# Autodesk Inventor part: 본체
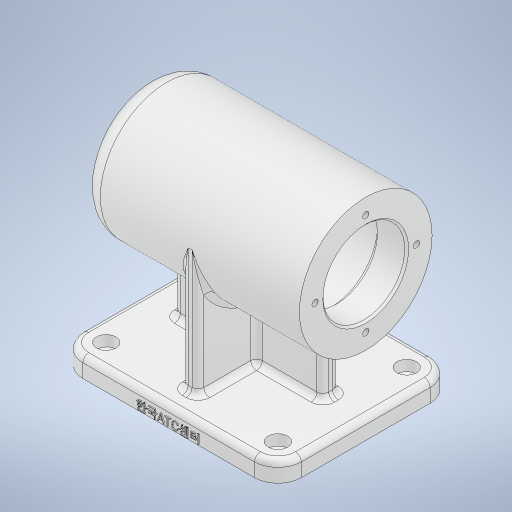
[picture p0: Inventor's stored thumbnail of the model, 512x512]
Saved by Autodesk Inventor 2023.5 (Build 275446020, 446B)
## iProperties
Created: 2026-08
Part Number: 본체
Material: 알루미늄 6061
Document SubType Name: Modeling
Designer: 1강의실14
Density: 2.7 g/cm^3
Appearance: 알루미늄 - 평지
Mass: 1025.89 g
Surface Area: 757.812 cm^2
Volume: 379.96 cm^3
Author: 1강의실14
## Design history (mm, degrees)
sketch "스케치1"
  geometry: L1 (56, 45)-(-56, 45); L2 (-56, 45)-(-56, -45); L3 (-56, -45)-(56, -45); L4 (56, -45)-(56, 45); L5 (56, 45)-(-56, -45); L6 (-56, 45)-(56, -45); 1 further point
  constraints: 12 end point, 2 midpoint, 2 parallel, 1 horizontal, 1 perpendicular
  dimensions: "d0" = 112 distance of L3.end L2.end; "d1" = 90 distance of L1.end L2.end
extrude "돌출1" new body sketch "스케치1" distance "d2" = 10; taper "d3" = 0 deg
sketch "스케치2"
  geometry: L1 (0, 0)-(0, 74); L2 (0, 74)-(44.651, 74); L3 (56, 0)-(-56, 0) reference; L4 (-46, 108)-(56, 108); L5 (56, 108)-(56, 96); L6 (55, 95)-(41, 95); L7 (41, 95)-(41, 95); L8 (38, 98)-(-10, 98); L9 (-13, 95)-(-13, 95); L10 (-13, 95)-(-24.4, 95); L11 (-25, 94.4)-(-25, 91.5); L12 (-25, 91.5)-(-43, 91.5); L13 (-43, 91.5)-(-43, 90); L14 (-43, 90)-(-46.4, 90); L15 (-50, 74)-(-56, 74); L16 (-56, 74)-(-56, 98); L17 (-47, 89.4)-(-47, 84.5); L18 (-47, 84.5)-(-47, 84.5); L19 (-50, 81.5)-(-50, 74); L20 (55, 95)-(56, 96); A1 r 0.6 centre (-46.4, 89.4) between (-46.4, 90) and (-47, 89.4); A2 r 0.6 centre (-24.4, 94.4) between (-24.4, 95) and (-25, 94.4); A3 r 10 centre (-46, 98) between (-46, 108) and (-56, 98); A4 r 3 centre (-10, 95) between (-10, 98) and (-13, 95); A5 r 3 centre (38, 95) between (41, 95) and (38, 98); A6 r 3 centre (-47, 81.5) between (-47, 84.5) and (-50, 81.5); 12 further points
  constraints: 38 end point, 16 point on line, 14 perpendicular, 12 point on circle, 12 tangent, 6 centre point, 2 collinear, 2 midpoint, 2 vertical, 1 equal radius, 1 horizontal
  dimensions: "d4" = 74 distance between parallel lines of L2 L3; "d5" = 112 distance of point (-56, 108) L4.end; "d6" = 54 distance of point (41, 98) point (-13, 98); "d7" = 15 distance of point (56, 95) L6.end; "d8" = 18 distance of L11.end L12.end; "d9" = 103 horizontal distance of point (56, 95) point (-47, 90); "d10" = 42 diameter of point (48, 95) L2; "d11" = 68 diameter of L4 L2; "d12" = 48 diameter of L8 L2; "d17" = 81 horizontal distance of L4.end point (-25, 95); "d18" = 3 distance of L17.end point (-50, 84.5); "d19" = 21 diameter of L18 L2; "d20" = 32 diameter of L14 L2; "d21" = 35 diameter of L12 L2; "d22" = 0.6 radius of A1; "d23" = 0.6 radius of A2 (derived); "d24" = 10 radius of A3 (derived); "d25" = 3 radius of A4; "d26" = 1 distance of L6.start point (56, 95); "d27" = 1 distance of L5.end point (56, 95) (= d26); "d28" = 3 radius of A6 (derived); "d64" = 56 distance between parallel lines of L1 L5
revolve "회전1" sketch "스케치2" stored, may be unused: angle "d29" = 90 deg
sketch "스케치3"
  geometry: L1 (56, -45)-(56, 45) reference; L2 (-56, -45)-(56, -45) reference; L3 (-56, 45)-(-56, -45) reference; L4 (56, 45)-(-56, 45) reference; L5 (0, 0)-(19.584, 0); L6 (0, 0)-(0, 15.112); 4 further points
  constraints: 4 end point, 2 symmetric about line, 1 horizontal, 1 vertical, 1 vertical alignment
  dimensions: "d30" = 66 distance of point (44, -33) point (44, 33); "d31" = 44 distance from line of L6 point (44, -33); "d32" = 33 distance from line of point (44, -33) L5
hole "구멍1" sketch "스케치3" at (44, 33), (44, -33), (-44, 33), (-44, -33) diameter "d33" = 5.5; stored, may be unused: countersink angle "d37" = 90 deg, drill point angle "d39" = 118 deg; dims "d34" = 9, "d35" = 10, "d36" = 5.5, "d38" = 11
fillet "모깎기1" dims "d40" = 12
sketch "스케치4"
  geometry: L1 (44, 45)-(-44, 45) reference; L2 (-56, 33)-(-56, -33) reference; L3 (-44, -45)-(44, -45) reference; L4 (56, -33)-(56, 33) reference; C1 r 5 at (-44, 33) reference; C2 r 5 at (44, 33) reference; C3 r 5 at (44, -33) reference; C4 r 5 at (-44, -33) reference; A1 r 12 centre (44, 33) between (56, 33) and (44, 45) reference; A2 r 12 centre (-44, 33) between (-44, 45) and (-56, 33) reference; A3 r 12 centre (-44, -33) between (-56, -33) and (-44, -45) reference; A4 r 12 centre (44, -33) between (44, -45) and (56, -33) reference; 1 further point
sketch "스케치5"
  geometry: L1 (-4, 34)-(4, 34); L2 (4, 34)-(4, -34); L3 (4, -34)-(-4, -34); L4 (-4, -34)-(-4, 34); L5 (-4, 34)-(4, -34); L6 (4, 34)-(-4, -34); L7 (-38, 4)-(38, 4); L8 (38, 4)-(38, -4); L9 (38, -4)-(-38, -4); L10 (-38, -4)-(-38, 4); L11 (-38, 4)-(38, -4); L12 (38, 4)-(-38, -4); 5 further points
  constraints: 24 end point, 4 midpoint, 4 parallel, 2 horizontal, 2 perpendicular
  dimensions: "d41" = 8 distance of L2.end L3.end; "d42" = 68 distance of L1.end L2.end; "d43" = 76 distance of L8.end L9.end; "d44" = 8 distance of L7.end L8.end
extrude "돌출2" join sketch "스케치5" stored distance "d45" = 10; taper "d46" = 0 deg
sketch "스케치6" dims "d47" = 52
  geometry: C1 r 34 at (0, 0) reference; C2 r 22 at (0, 0) reference; 6 further points
  constraints: 2 vertical alignment, 1 coincident, 7 other
  dimensions: "d50" = 360 deg dimension on C2.centre point (0, 26) (derived)
hole "구멍2" sketch "스케치6" at (0, 26), (-26, 0), (0, -26), (26, 0) diameter "d52" = 3.242; stored, may be unused: countersink angle "d56" = 90 deg, drill point angle "d58" = 118 deg; dims "d53" = 8, "d54" = 10, "d55" = 5.5, "d57" = 10
fillet "모깎기2" dims "d59" = 3
fillet "모깎기3" dims "d60" = 3
sketch "스케치7"
  geometry: L1 (0, 0)-(88, 0) reference; L2 (0, 0)-(-12, 0) reference; 3 further points
  constraints: 1 midpoint, 1 vertical alignment, 1 other
  dimensions: "d61" = 3 distance from line of L2 point (44, 3)
feature "엠보싱1" sketch "스케치7" dims "d0" = 112, "d1" = 90, "d9" = 103, "d62" = 0.5, "d63" = 0
node "솔리드1"
node "투영된 루프1"
feature "A9D066F2-1C7D-4E18-AEED-F7BC21143FA4" dims "d33" = 5.5, "d34" = 9, "d35" = 10, "d36" = 5.5, "d37" = 90 deg, "d38" = 11, "d39" = 118 deg
